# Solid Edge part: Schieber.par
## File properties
Author: helmut
Template: Normal.par
Last saved by: helmut
Revision: 3
Application: Solid Edge
Teilflächenrmatvorlage: Model Default
Coef. of Thermal Exp: 0.0
Thermal Conductivity: 0.0
Specific Heat: 0.0
Modulus of Elasticity: 0.0
Poission's Ratio: 0.0
Yield Stress: 0.0
Ultimate Stress: 0.0
Elongation: 0.0
Dichte: 7,79999702546 kg/dm^3
Genauigkeit: 0,010
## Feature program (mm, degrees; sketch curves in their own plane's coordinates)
sketch for "unnamed Protrusion 1" plane through (0, 0, 0) normal (0, -1, 0) x-axis (1, 0, 0)
  line (-19, 0) -> (19, 0)
  line (19, 0) -> (19, 9.12)
  line (19, 9.12) -> (9.5, 9.12)
  line (9.5, 9.12) -> (9.5, 19)
  line (9.5, 19) -> (-9.5, 19)
  line (-9.5, 19) -> (-9.5, 9)
  line (-9.5, 9) -> (-19, 9)
  line (-19, 9) -> (-19, 0)
  dimension (linear) = 9.5
  dimension (linear) = 9.5
  dimension (linear) = 19
extrude "unnamed Protrusion 1" add finite 50 symmetric
sketch for "Bohrung_1" plane through (0, 0, 19) normal (0, 0, 1) x-axis (0, 1, 0)
  hole centre (0, 0) bore radius 3
hole "Bohrung_1" diameter 6 through
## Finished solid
Body 1: solid body, 11 faces, 26 edges, 16 vertices.
  Faces by surface: plane 10, cylinder 1
  Edges by curve: line 24, circle 2
Bounding box of the edges (mm): 38.000 x 50.000 x 19.000, from (-19, -25, 0) to (19, 25, 19).
Cylindrical faces by radius (mm): R3 x1
Planar faces by outward normal: +x 2, +y 1, +z 3, -x 2, -y 1, -z 1
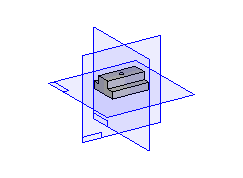
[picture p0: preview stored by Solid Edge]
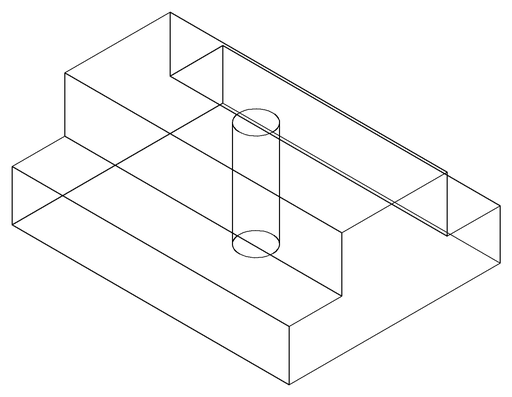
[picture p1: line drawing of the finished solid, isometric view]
